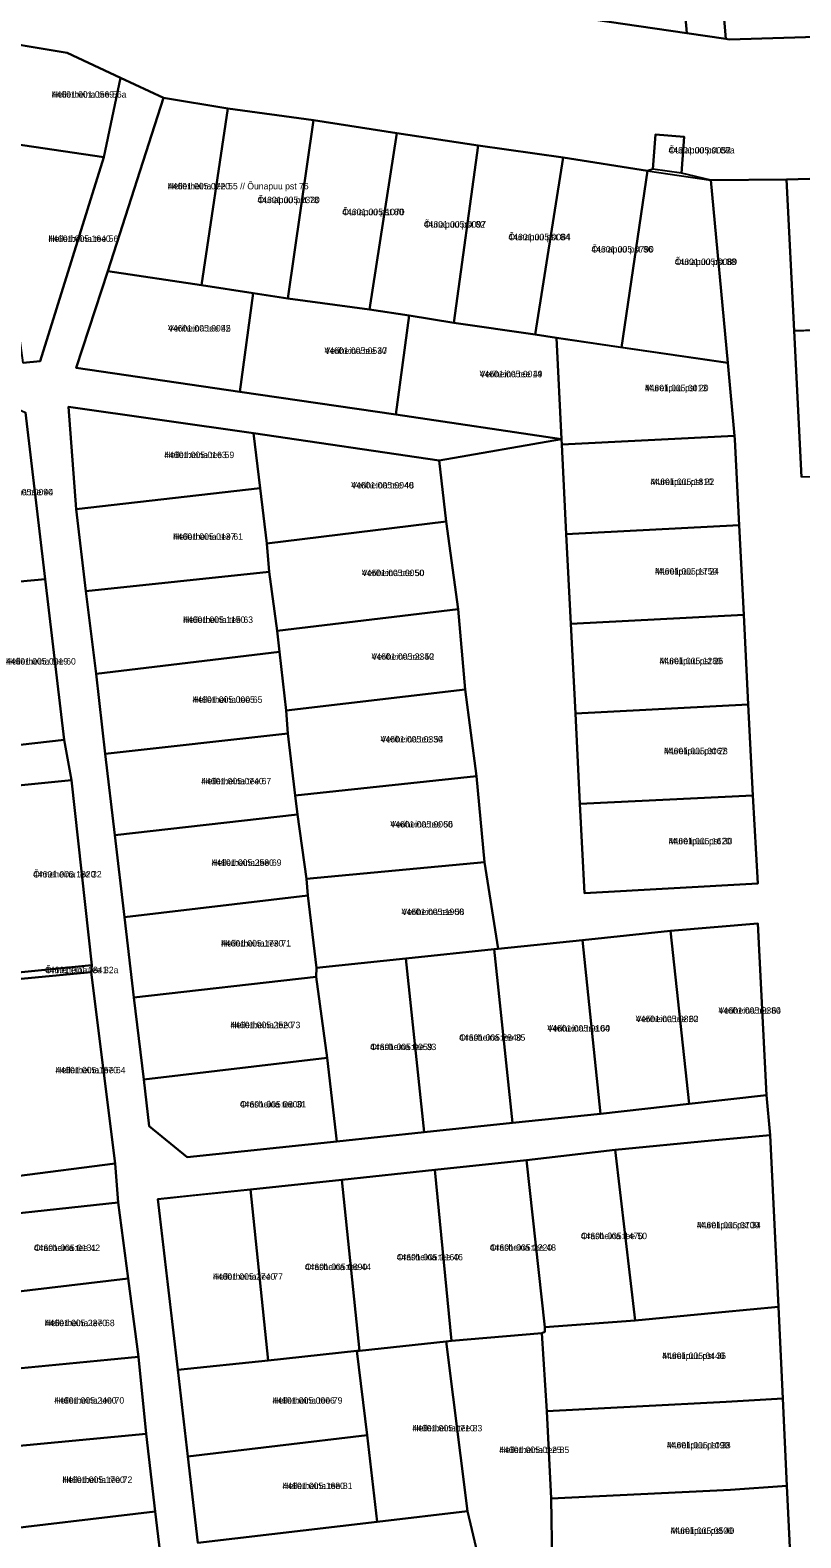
# Model space of a CAD drawing. Extents: x 551843 to 558501, y 6589003 to 6595718.
# Drawn here: x 553010 to 553189.3, y 6592837.4 to 6593188.1 of the extents above; entities that cross this region are included whole.
import ezdxf

# ---------------------------------------------------------------- set-up
doc = ezdxf.new("R2010")
doc.units = 0
for name, color, linetype in [('L_AADRESS', 7, 'Continuous'), ('PIIR', 7, 'Continuous'), ('TUNNUS', 7, 'Continuous')]:
    doc.layers.add(name, color=color, linetype=linetype)

msp = doc.modelspace()

# ---------------------------------------------------------------- linework, layer by layer
at = {"layer": 'PIIR'}
for points in [[(553138.6, 6593225.34), (553142.22, 6593224.87), (553153.51, 6593223.4), (553159.76, 6593222.2), (553162.74, 6593187.4), (553133.54, 6593191.68)], [(553168.98, 6593219.85), (553194.54, 6593220.58), (553195.51, 6593186.59), (553172.63, 6593185.94), (553171.88, 6593186.05)], [(553030.99, 6593177.02), (553027.1, 6593158.56), (553001.28, 6593162.32), (552998.09, 6593186.23), (553018.59, 6593182.86)], [(553055.93, 6593169.86), (553049.8, 6593128.81), (553028.04, 6593132.03), (553040.97, 6593172.32)], [(553055.93, 6593169.86), (553075.92, 6593167.19), (553069.9, 6593125.69), (553061.89, 6593126.93), (553049.8, 6593128.81)], [(553095.28, 6593164.17), (553088.95, 6593123.1), (553069.9, 6593125.69), (553075.92, 6593167.19)], [(553088.95, 6593123.1), (553095.28, 6593164.17), (553114.18, 6593161.25), (553108.53, 6593119.99), (553098.13, 6593121.73)], [(553162.16, 6593163.31), (553161.52, 6593154.87), (553154.89, 6593155.73), (553155.5, 6593163.81)], [(553003.1, 6593149.18), (553001.28, 6593162.32), (553027.1, 6593158.56), (553012.28, 6593111.12), (553008.31, 6593110.7)], [(553133.98, 6593158.48), (553127.51, 6593117.33), (553108.53, 6593119.99), (553114.18, 6593161.25)], [(553133.98, 6593158.48), (553153.63, 6593155.37), (553147.6, 6593114.3), (553132.44, 6593116.52), (553127.51, 6593117.33)], [(553153.63, 6593155.37), (553168.36, 6593153.21), (553172.32, 6593110.68), (553147.6, 6593114.3)], [(553210.5, 6593154.04), (553211.49, 6593118.86), (553187.74, 6593118.19), (553185.99, 6593153.35)], [(553028.04, 6593132.03), (553049.8, 6593128.81), (553061.89, 6593126.93), (553058.76, 6593103.97), (553020.64, 6593109.56)], [(553061.89, 6593126.93), (553069.9, 6593125.69), (553088.95, 6593123.1), (553098.13, 6593121.73), (553095.06, 6593098.66), (553058.76, 6593103.97)], [(553133.61, 6593092.99), (553095.06, 6593098.66), (553098.13, 6593121.73), (553108.53, 6593119.99), (553127.51, 6593117.33), (553132.44, 6593116.52)], [(553189.43, 6593084.14), (553187.74, 6593118.19), (553212.45, 6593118.99), (553213.88, 6593119.02), (553214.85, 6593084.85)], [(553172.32, 6593110.68), (553173.89, 6593093.76), (553133.68, 6593091.69), (553133.61, 6593092.99), (553132.44, 6593116.52)], [(553005.02, 6593100.97), (553008.91, 6593099.16), (553013.43, 6593060.38), (552992.62, 6593058.48), (552988.08, 6593099.36)], [(553018.85, 6593100.45), (553061.91, 6593094.33), (553063.45, 6593081.52), (553020.64, 6593076.66)], [(553063.45, 6593081.52), (553061.91, 6593094.33), (553105.15, 6593088), (553106.78, 6593073.82), (553065.02, 6593068.65)], [(553133.68, 6593091.69), (553173.89, 6593093.76), (553173.97, 6593092.87), (553174.97, 6593072.93), (553134.73, 6593070.84)], [(553022.93, 6593057.57), (553020.64, 6593076.66), (553063.45, 6593081.52), (553065.02, 6593068.65), (553065.59, 6593062.06)], [(553065.59, 6593062.06), (553065.02, 6593068.65), (553106.78, 6593073.82), (553109.55, 6593053.44), (553067.48, 6593048.38)], [(553134.73, 6593070.84), (553174.97, 6593072.93), (553176.02, 6593052.08), (553135.78, 6593049.99)], [(553022.93, 6593057.57), (553065.59, 6593062.06), (553067.48, 6593048.38), (553068.01, 6593043.52), (553025.33, 6593038.36)], [(553017.86, 6593023.03), (552994.64, 6593020.4), (552990.74, 6593058.12), (552992.62, 6593058.48), (553013.43, 6593060.38)], [(553068.01, 6593043.52), (553067.48, 6593048.38), (553109.55, 6593053.44), (553111.19, 6593034.72), (553069.57, 6593029.82)], [(553135.78, 6593049.99), (553176.02, 6593052.08), (553177.06, 6593031.23), (553136.83, 6593029.14)], [(553068.01, 6593043.52), (553069.57, 6593029.82), (553069.95, 6593024.47), (553027.43, 6593019.73), (553025.33, 6593038.36)], [(553069.95, 6593024.47), (553069.57, 6593029.82), (553111.19, 6593034.72), (553113.81, 6593014.55), (553071.61, 6593010.09)], [(553177.06, 6593031.23), (553178.13, 6593010.08), (553137.84, 6593008.1), (553136.83, 6593029.14)], [(553027.43, 6593019.73), (553069.95, 6593024.47), (553071.61, 6593010.09), (553072.17, 6593005.61), (553029.63, 6593000.85)], [(552996.99, 6593011.42), (553019.58, 6593013.61), (553024.28, 6592970.62), (553001.62, 6592968.34)], [(553072.17, 6593005.61), (553071.61, 6593010.09), (553113.81, 6593014.55), (553115.7, 6592994.58), (553074.27, 6592990.68)], [(553178.13, 6593010.08), (553179.33, 6592989.6), (553138.93, 6592987.35), (553137.84, 6593008.1)], [(553029.63, 6593000.85), (553072.17, 6593005.61), (553074.27, 6592990.68), (553074.61, 6592986.81), (553031.93, 6592981.78)], [(553074.61, 6592986.81), (553074.27, 6592990.68), (553115.7, 6592994.58), (553118.87, 6592974.39), (553117.94, 6592974.29), (553097.4, 6592972.14), (553076.6, 6592969.95)], [(553031.93, 6592981.78), (553074.61, 6592986.81), (553076.6, 6592969.95), (553076.53, 6592967.88), (553034.09, 6592963.05)], [(553138.47, 6592976.43), (553158.94, 6592978.61), (553163.3, 6592938.33), (553142.69, 6592936.01)], [(553179.31, 6592980.27), (553181.32, 6592940.34), (553163.3, 6592938.33), (553158.94, 6592978.61)], [(553117.94, 6592974.29), (553122.21, 6592933.9), (553101.63, 6592931.72), (553097.4, 6592972.14)], [(553122.21, 6592933.9), (553117.94, 6592974.29), (553118.87, 6592974.39), (553138.47, 6592976.43), (553142.69, 6592936.01)], [(553079.07, 6592949.02), (553076.53, 6592967.88), (553076.6, 6592969.95), (553097.4, 6592972.14), (553101.63, 6592931.72), (553081.35, 6592929.6)], [(553002.02, 6592966.84), (553001.62, 6592968.34), (553024.28, 6592970.62), (553024.12, 6592969)], [(553006.83, 6592921.54), (553002.29, 6592964.33), (553002.02, 6592966.84), (553024.12, 6592969), (553029.73, 6592924.42)], [(553076.53, 6592967.88), (553079.07, 6592949.02), (553036.39, 6592943.99), (553034.09, 6592963.05)], [(553081.35, 6592929.6), (553046.5, 6592925.96), (553037.67, 6592933.18), (553036.39, 6592943.99), (553079.07, 6592949.02)], [(553146.12, 6592927.67), (553168.52, 6592929.79), (553182.15, 6592931.08), (553184.11, 6592891.13), (553170.92, 6592889.85), (553150.76, 6592887.94)], [(553125.45, 6592925.27), (553129.74, 6592886.36), (553129.73, 6592885.27), (553129.04, 6592884.96), (553108.03, 6592883.24), (553104.11, 6592922.98)], [(553150.76, 6592887.94), (553129.74, 6592886.36), (553125.45, 6592925.27), (553146.12, 6592927.67)], [(553104.11, 6592922.98), (553108.03, 6592883.24), (553106.79, 6592883.08), (553086.58, 6592880.88), (553082.51, 6592920.66)], [(553039.64, 6592916.16), (553047.53, 6592916.99), (553061.2, 6592918.43), (553065.36, 6592878.64), (553044.3, 6592876.44), (553040.57, 6592908.25)], [(553061.2, 6592918.43), (553082.51, 6592920.66), (553086.58, 6592880.88), (553086.01, 6592880.85), (553065.36, 6592878.64)], [(552988.7, 6592910.87), (553030.42, 6592915.42), (553032.78, 6592897.69), (552991.5, 6592892.8)], [(553035.16, 6592879.51), (552994.18, 6592875.56), (552991.5, 6592892.8), (553032.78, 6592897.69)], [(553129.04, 6592884.96), (553129.73, 6592885.27), (553129.74, 6592886.36), (553150.76, 6592887.94), (553170.92, 6592889.85), (553184.11, 6592891.13), (553185.13, 6592869.82), (553171.96, 6592868.99), (553130.17, 6592866.84)], [(553088.36, 6592861.24), (553086.01, 6592880.85), (553086.58, 6592880.88), (553106.79, 6592883.08), (553111.77, 6592843.56), (553090.73, 6592841.1)], [(553106.79, 6592883.08), (553108.03, 6592883.24), (553129.04, 6592884.96), (553130.17, 6592866.84), (553131.24, 6592846.54), (553131.45, 6592831.76), (553115.06, 6592829.5), (553111.77, 6592843.56)], [(553046.66, 6592856.33), (553044.3, 6592876.44), (553065.36, 6592878.64), (553086.01, 6592880.85), (553088.36, 6592861.24)], [(553036.95, 6592861.6), (552995.89, 6592857.68), (552994.73, 6592870.04), (552994.15, 6592875.56), (553035.16, 6592879.51)], [(553171.96, 6592868.99), (553185.13, 6592869.82), (553186.06, 6592849.5), (553172.95, 6592848.52), (553131.24, 6592846.54), (553130.17, 6592866.84)], [(552995.89, 6592857.68), (553036.95, 6592861.6), (553039.09, 6592843.47), (552998.37, 6592838.7), (552996.82, 6592847.98)], [(553046.66, 6592856.33), (553088.36, 6592861.24), (553090.73, 6592841.1), (553049.01, 6592836.22)], [(553131.24, 6592846.54), (553172.95, 6592848.52), (553186.06, 6592849.5), (553186.98, 6592830.44), (553173.87, 6592829.55), (553131.49, 6592827.09), (553131.45, 6592831.76)], [(552998.37, 6592838.7), (553039.09, 6592843.47), (553041.21, 6592825.44), (553000.49, 6592820.67), (552999.69, 6592827.58)]]:
    msp.add_lwpolyline(points, close=True, dxfattribs=at)
for points in [[(553168.98, 6593219.85), (553171.88, 6593186.05), (553162.74, 6593187.4), (553159.76, 6593222.2)], [(553210.5, 6593154.04), (553185.99, 6593153.35), (553168.36, 6593153.21), (553161.52, 6593154.87), (553162.16, 6593163.31), (553155.5, 6593163.81), (553154.89, 6593155.73), (553153.63, 6593155.37), (553133.98, 6593158.48), (553114.18, 6593161.25), (553095.28, 6593164.17), (553075.92, 6593167.19), (553055.93, 6593169.86), (553040.97, 6593172.32), (553030.99, 6593177.02), (553018.59, 6593182.86), (552998.09, 6593186.23), (552974.33, 6593193.77)], [(553133.54, 6593191.68), (553162.74, 6593187.4), (553171.88, 6593186.05), (553172.63, 6593185.94), (553195.51, 6593186.59)], [(553008.31, 6593110.7), (553012.28, 6593111.12), (553027.1, 6593158.56), (553030.99, 6593177.02), (553040.97, 6593172.32), (553028.04, 6593132.03), (553020.64, 6593109.56), (553058.76, 6593103.97), (553095.06, 6593098.66), (553133.61, 6593092.99), (553105.15, 6593088), (553061.91, 6593094.33), (553018.85, 6593100.45), (553020.64, 6593076.66), (553022.93, 6593057.57), (553025.33, 6593038.36), (553027.43, 6593019.73), (553029.63, 6593000.85), (553031.93, 6592981.78), (553034.09, 6592963.05), (553036.39, 6592943.99), (553037.67, 6592933.18), (553046.5, 6592925.96), (553081.35, 6592929.6), (553101.63, 6592931.72), (553122.21, 6592933.9), (553142.69, 6592936.01), (553163.3, 6592938.33), (553181.32, 6592940.34), (553182.15, 6592931.08), (553168.52, 6592929.79), (553146.12, 6592927.67), (553125.45, 6592925.27), (553104.11, 6592922.98), (553082.51, 6592920.66), (553061.2, 6592918.43), (553039.64, 6592916.16), (553044.3, 6592876.44), (553046.66, 6592856.33), (553049.01, 6592836.22), (553090.73, 6592841.1), (553111.77, 6592843.56), (553115.06, 6592829.5)], [(553186.98, 6592830.44), (553186.06, 6592849.5), (553185.13, 6592869.82), (553184.11, 6592891.13), (553182.15, 6592931.08), (553181.32, 6592940.34), (553179.31, 6592980.27), (553158.94, 6592978.61), (553138.47, 6592976.43), (553118.87, 6592974.39), (553115.7, 6592994.58), (553113.81, 6593014.55), (553111.19, 6593034.72), (553109.55, 6593053.44), (553106.78, 6593073.82), (553105.15, 6593088), (553133.61, 6593092.99), (553133.68, 6593091.69), (553134.73, 6593070.84), (553135.78, 6593049.99), (553136.83, 6593029.14), (553137.84, 6593008.1), (553138.93, 6592987.35), (553179.33, 6592989.6), (553178.13, 6593010.08), (553177.06, 6593031.23), (553176.02, 6593052.08), (553174.97, 6593072.93), (553173.97, 6593092.87), (553173.89, 6593093.76), (553172.32, 6593110.68), (553168.36, 6593153.21), (553185.99, 6593153.35), (553187.74, 6593118.19), (553189.43, 6593084.14)], [(553041.21, 6592825.44), (553039.09, 6592843.47), (553036.95, 6592861.6), (553035.16, 6592879.51), (553032.78, 6592897.69), (553030.42, 6592915.42), (553029.73, 6592924.42), (553024.12, 6592969), (553024.28, 6592970.62), (553019.58, 6593013.61), (553017.86, 6593023.03), (553013.43, 6593060.38), (553008.91, 6593099.16)], [(552994.64, 6593020.4), (553017.86, 6593023.03), (553019.58, 6593013.61), (552996.99, 6593011.42)], [(553006.83, 6592921.54), (553029.73, 6592924.42), (553030.42, 6592915.42), (552988.7, 6592910.87)]]:
    msp.add_lwpolyline(points, dxfattribs=at)

# ---------------------------------------------------------------- texts
at = {"layer": 'L_AADRESS'}
for s, p in [('Hellerheina tee 56a', (553014.98, 6593172.4)), ('Õunapuu pst 88a', (553158.52, 6593159.42)), ('Hellerheina tee 55 // Õunapuu pst 76', (553041.98, 6593151.06)), ('Õunapuu pst 78', (553062.86, 6593147.86)), ('Õunapuu pst 80', (553082.59, 6593145.06)), ('Õunapuu pst 82', (553101.57, 6593142.18)), ('Hellerheina tee 56', (553014.19, 6593138.84)), ('Õunapuu pst 84', (553121.25, 6593139.23)), ('Õunapuu pst 86', (553140.57, 6593136.38)), ('Õunapuu pst 88', (553159.96, 6593133.47)), ('Veriheina tee 45', (553042.05, 6593118)), ('Veriheina tee 47', (553078.45, 6593112.79)), ('Veriheina tee 49', (553114.56, 6593107.36)), ('Murelipuu pst 20', (553152.99, 6593104.11)), ('Hellerheina tee 59', (553041.17, 6593088.55)), ('Veriheina tee 48', (553084.68, 6593081.49)), ('Murelipuu pst 22', (553154.33, 6593082.3)), ('Veriheina tee 44', (553000.75, 6593079.89)), ('Hellerheina tee 61', (553043.2, 6593069.54)), ('Veriheina tee 50', (553087.12, 6593061.1)), ('Murelipuu pst 24', (553155.38, 6593061.46)), ('Hellerheina tee 63', (553045.54, 6593050.21)), ('Hellerheina tee 60', (553004.3, 6593040.52)), ('Veriheina tee 52', (553089.4, 6593041.63)), ('Murelipuu pst 26', (553156.42, 6593040.61)), ('Hellerheina tee 65', (553047.73, 6593031.62)), ('Veriheina tee 54', (553091.49, 6593022.4)), ('Murelipuu pst 28', (553157.46, 6593019.67)), ('Hellerheina tee 67', (553049.78, 6593012.66)), ('Veriheina tee 56', (553093.77, 6593002.62)), ('Murelipuu pst 30', (553158.56, 6592998.71)), ('Hellerheina tee 69', (553052.17, 6592993.7)), ('Õnneheina tee 32', (553010.64, 6592990.99)), ('Veriheina tee 58', (553096.39, 6592982.26)), ('Hellerheina tee 71', (553054.37, 6592974.93)), ('Õnneheina tee 32a', (553013.43, 6592968.73)), ('Veriheina tee 64', (553170.13, 6592959.31)), ('Hellerheina tee 73', (553056.54, 6592955.93)), ('Veriheina tee 60', (553130.31, 6592955.16)), ('Veriheina tee 62', (553150.88, 6592957.34)), ('Orasheina tee 35', (553109.8, 6592953.01)), ('Orasheina tee 33', (553089.08, 6592950.84)), ('Hellerheina tee 64', (553015.88, 6592945.44)), ('Orasheina tee 31', (553058.79, 6592937.49)), ('Orasheina tee 50', (553138.11, 6592906.86)), ('Murelipuu pst 34', (553165.11, 6592909.38)), ('Orasheina tee 42', (553010.84, 6592904.11)), ('Orasheina tee 48', (553116.93, 6592904.16)), ('Orasheina tee 44', (553073.89, 6592899.66)), ('Orasheina tee 46', (553095.27, 6592901.93)), ('Hellerheina tee 77', (553052.5, 6592897.41)), ('Hellerheina tee 68', (553013.34, 6592886.62)), ('Murelipuu pst 36', (553157.05, 6592878.99)), ('Hellerheina tee 70', (553015.56, 6592868.6)), ('Hellerheina tee 79', (553066.35, 6592868.59)), ('Hellerheina tee 83', (553098.89, 6592862.14)), ('Hellerheina tee 85', (553119.12, 6592857.1)), ('Murelipuu pst 38', (553158.14, 6592858.18)), ('Hellerheina tee 72', (553017.46, 6592850.15)), ('Hellerheina tee 81', (553068.69, 6592848.73)), ('Murelipuu pst 40', (553158.98, 6592838.29))]:
    msp.add_text(s, height=1.5, dxfattribs=at).set_placement(p)
at = {"layer": 'TUNNUS'}
for s, p in [('44601:001:0569', (553014.98, 6593172.4)), ('44601:005:0052', (553158.52, 6593159.42)), ('44601:005:0720', (553041.98, 6593151.06)), ('44601:005:2320', (553062.86, 6593147.86)), ('44601:005:1070', (553082.59, 6593145.06)), ('44601:005:0097', (553101.57, 6593142.18)), ('44601:005:1640', (553014.19, 6593138.84)), ('44601:005:0084', (553121.25, 6593139.23)), ('44601:005:0790', (553140.57, 6593136.38)), ('44601:005:0089', (553159.96, 6593133.47)), ('44601:005:0082', (553042.05, 6593118)), ('44601:005:0530', (553078.45, 6593112.79)), ('44601:005:0014', (553114.56, 6593107.36)), ('44601:005:0013', (553152.99, 6593104.11)), ('44601:005:0163', (553041.17, 6593088.55)), ('44601:005:0040', (553084.68, 6593081.49)), ('44601:005:1810', (553154.33, 6593082.3)), ('44601:005:0090', (553000.75, 6593079.89)), ('44601:005:0137', (553043.2, 6593069.54)), ('44601:005:0050', (553087.12, 6593061.1)), ('44601:005:1750', (553155.38, 6593061.46)), ('44601:005:1150', (553045.54, 6593050.21)), ('44601:005:0019', (553004.3, 6593040.52)), ('44601:005:2340', (553089.4, 6593041.63)), ('44601:005:1280', (553156.42, 6593040.61)), ('44601:005:0005', (553047.73, 6593031.62)), ('44601:005:0330', (553091.49, 6593022.4)), ('44601:005:0067', (553157.46, 6593019.67)), ('44601:005:0740', (553049.78, 6593012.66)), ('44601:005:0060', (553093.77, 6593002.62)), ('44601:005:1620', (553158.56, 6592998.71)), ('44601:005:1320', (553010.64, 6592990.99)), ('44601:005:2580', (553052.17, 6592993.7)), ('44601:005:1900', (553096.39, 6592982.26)), ('44601:005:1730', (553054.37, 6592974.93)), ('44601:001:0841', (553013.43, 6592968.73)), ('44601:005:2380', (553170.13, 6592959.31)), ('44601:005:2520', (553056.54, 6592955.93)), ('44601:005:0104', (553130.31, 6592955.16)), ('44601:005:0820', (553150.88, 6592957.34)), ('44601:005:2840', (553109.8, 6592953.01)), ('44601:005:0059', (553089.08, 6592950.84)), ('44601:005:1670', (553015.88, 6592945.44)), ('44601:005:0800', (553058.79, 6592937.49)), ('44601:005:1470', (553138.11, 6592906.86)), ('44601:005:0700', (553165.11, 6592909.38)), ('44601:005:0131', (553010.84, 6592904.11)), ('44601:005:2220', (553116.93, 6592904.16)), ('44601:005:0890', (553073.89, 6592899.66)), ('44601:005:1160', (553095.27, 6592901.93)), ('44601:005:2740', (553052.5, 6592897.41)), ('44601:005:2370', (553013.34, 6592886.62)), ('44601:005:0440', (553157.05, 6592878.99)), ('44601:005:2400', (553015.56, 6592868.6)), ('44601:005:0006', (553066.35, 6592868.59)), ('44601:005:1710', (553098.89, 6592862.14)), ('44601:005:0125', (553119.12, 6592857.1)), ('44601:005:1090', (553158.14, 6592858.18)), ('44601:005:1700', (553017.46, 6592850.15)), ('44601:005:1680', (553068.69, 6592848.73)), ('44601:005:0500', (553158.98, 6592838.29))]:
    msp.add_text(s, height=1.5, dxfattribs=at).set_placement(p)

doc.saveas('drawing.dxf')
